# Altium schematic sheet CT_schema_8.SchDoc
size 278 x 170 mm
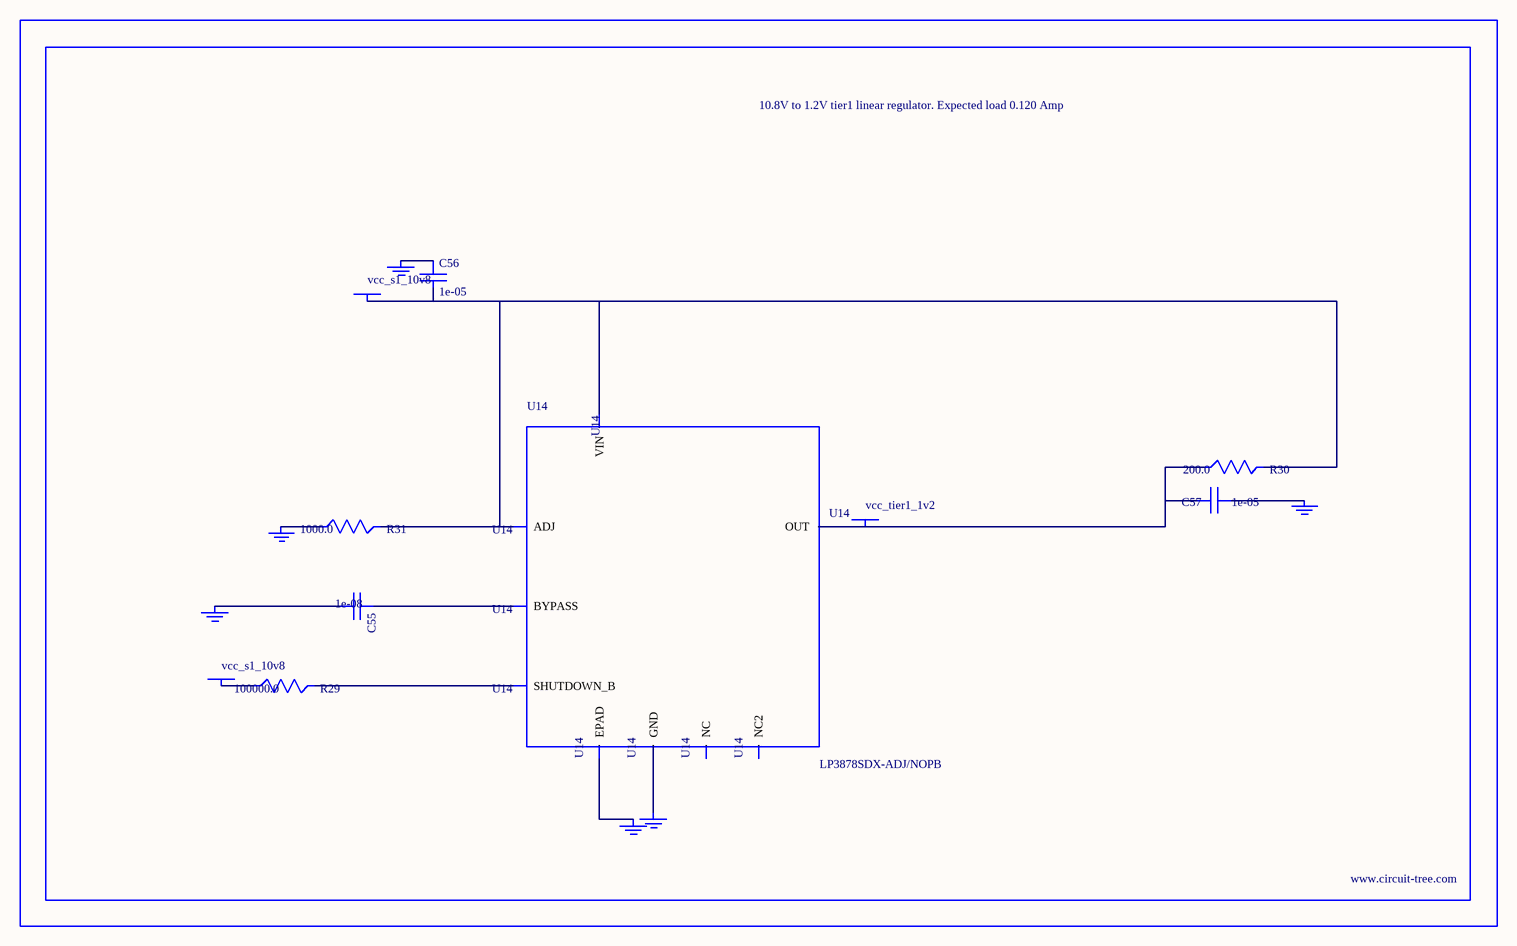
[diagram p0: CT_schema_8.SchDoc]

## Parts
BORDER7  (no value)
C55  1e-08  [C0402]
C56  1e-05  [C1206]
C57  1e-05  [C0805]
GND_INSTANCE_7_0  (no value)
GND_INSTANCE_7_1  (no value)
GND_INSTANCE_7_2  (no value)
GND_INSTANCE_7_3  (no value)
GND_INSTANCE_7_4  (no value)
GND_INSTANCE_7_5  (no value)
POWER_INSTANCE_7_0  vcc_s1_10v8
POWER_INSTANCE_7_1  vcc_s1_10v8
POWER_INSTANCE_7_2  vcc_tier1_1v2
R29  100000.0  [R0603]
R30  200.0  [R0603]
R31  1000.0  [R0603]
U14  LP3878SDX-ADJ/NOPB  [WSON-8]

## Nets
NetC55_1: C55.1 U14.1(BYPASS)
NetC55_2: C55.2 GND_INSTANCE_7_0.0(GND)
NetC56_1: C56.1 GND_INSTANCE_7_1.0(GND)
NetC56_2: C56.2 POWER_INSTANCE_7_0.0(PWR) R30.2 R31.2 U14.4(VIN) U14.6(ADJ)
NetC57_1: C57.1 GND_INSTANCE_7_2.0(GND)
NetC57_2: C57.2 POWER_INSTANCE_7_2.0(PWR) R30.1 U14.5(OUT)
NetGND_INSTANCE_7_3_0: GND_INSTANCE_7_3.0(GND) R31.1
NetGND_INSTANCE_7_4_0: GND_INSTANCE_7_4.0(GND) U14.PAD(EPAD)
NetGND_INSTANCE_7_5_0: GND_INSTANCE_7_5.0(GND) U14.3(GND)
NetPOWER_INSTANCE_7_1_0: POWER_INSTANCE_7_1.0(PWR) R29.1
NetR29_2: R29.2 U14.8(SHUTDOWN_B)

Not connected (* = marked no-connect by the designer): U14 2(NC) 7(NC2)

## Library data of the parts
BORDER7 = BORDER_PAGE7
C55 = C0402C103K3RAC
C56 = C1206C106K3RACTU
C57 = GRM219R60J106ME19D
GND_INSTANCE_7_0-GND_INSTANCE_7_5 = GND
POWER_INSTANCE_7_0-POWER_INSTANCE_7_2 = PWR
R29 = RC0603JR-07100KL
R30 = RC0603JR-07200RL
R31 = RC0603JR-071KL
